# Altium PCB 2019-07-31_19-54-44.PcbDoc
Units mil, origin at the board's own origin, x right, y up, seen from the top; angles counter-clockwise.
Board outline 1400 x 2000 mil, 4 copper layers (Top Layer, MidLayer1, MidLayer2, Bottom Layer); 12 components, 5 nets, 24 pads, 20 vias.
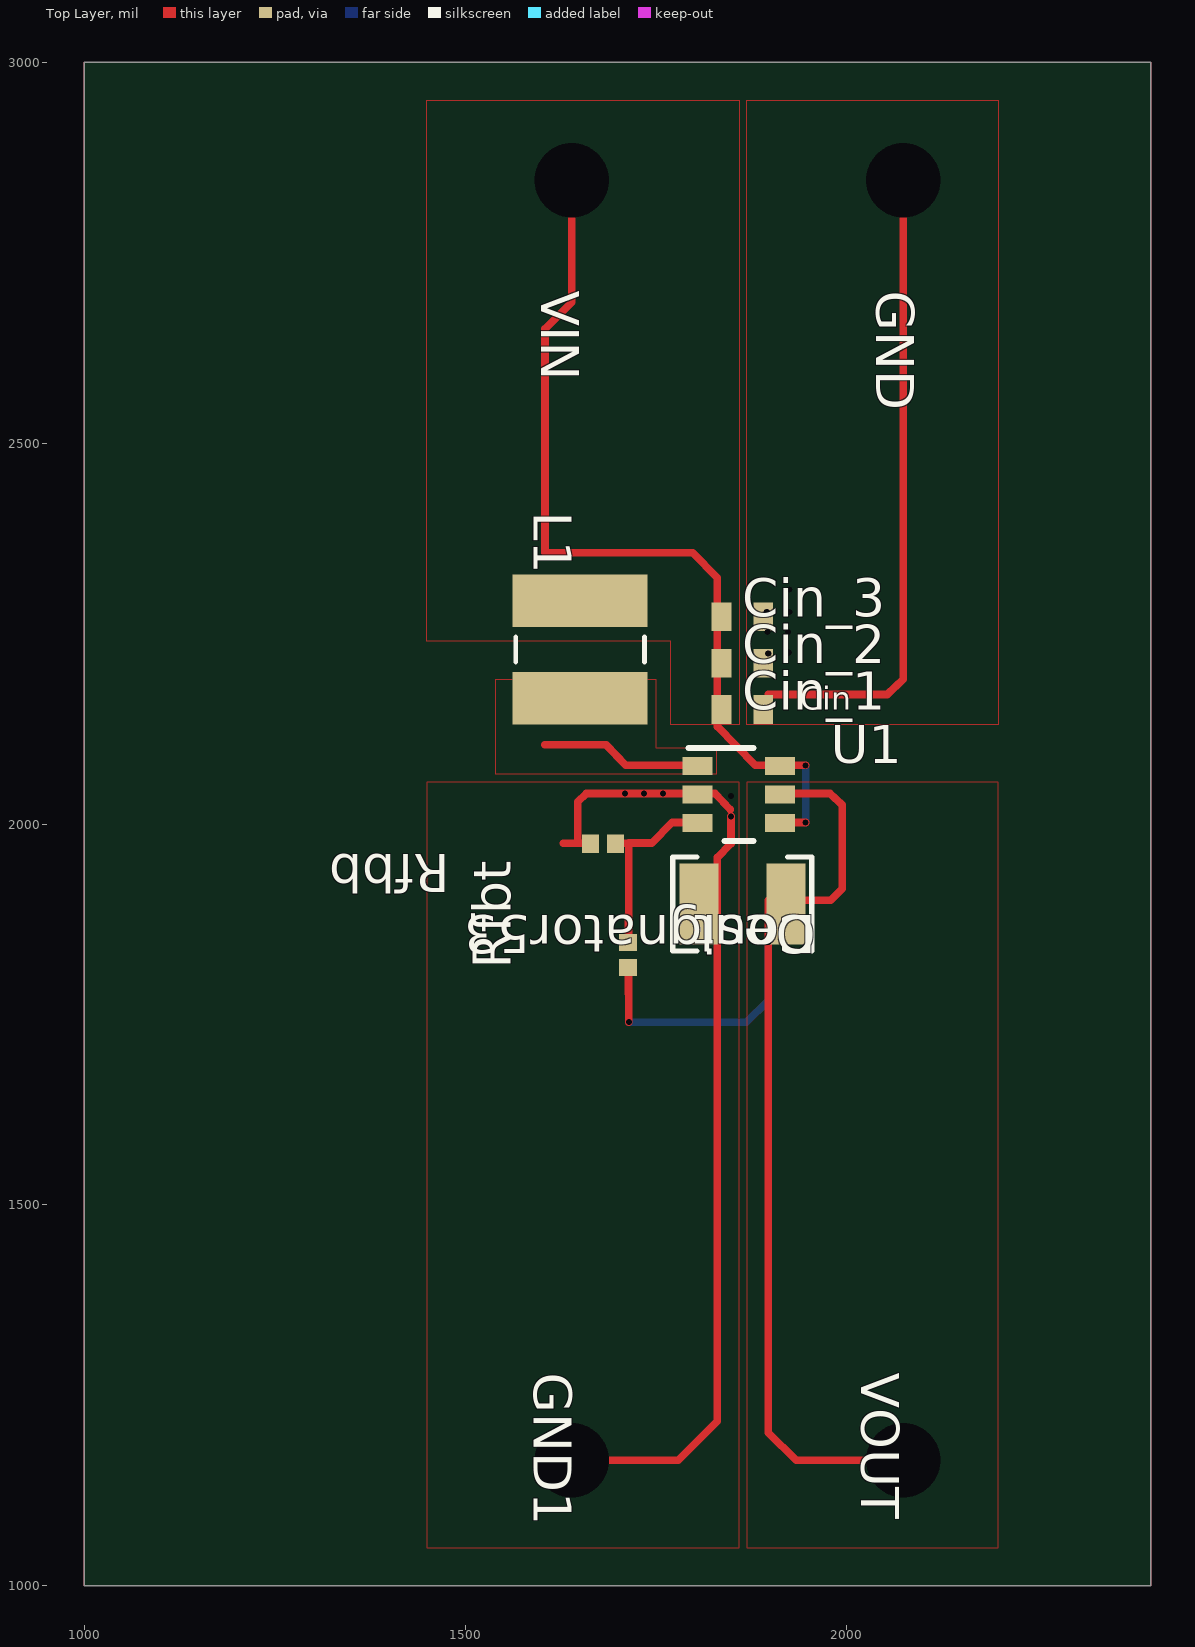
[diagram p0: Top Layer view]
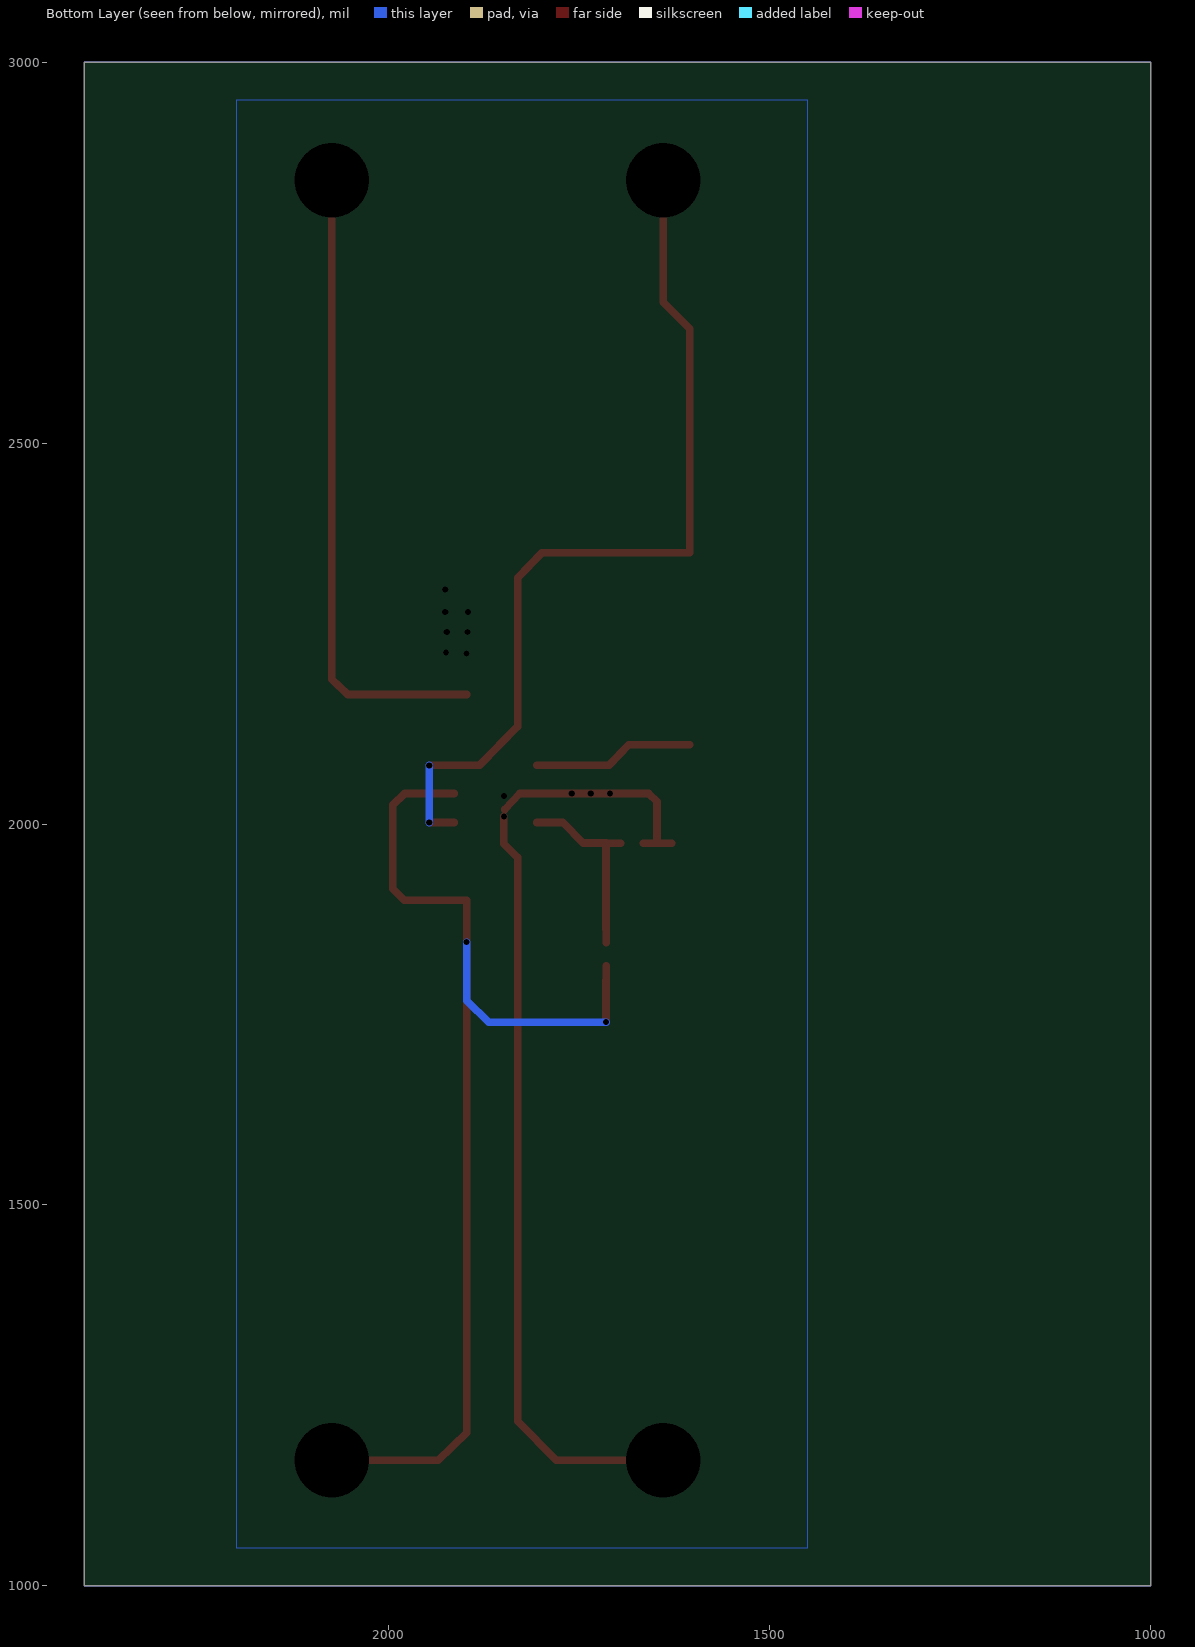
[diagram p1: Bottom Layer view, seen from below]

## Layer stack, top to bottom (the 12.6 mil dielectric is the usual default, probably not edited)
Top Layer: signal copper 1.4
Dielectric: core 12.6, FR-4, Dk 4.8
MidLayer1: signal copper 1.4
Dielectric: prepreg 12.6, FR-4, Dk 4.8
MidLayer2: signal copper 1.4
Dielectric: core 12.6, FR-4, Dk 4.8
Bottom Layer: signal copper 1.4

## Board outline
1000,1000 2400,1000 2400,3000 1000,3000

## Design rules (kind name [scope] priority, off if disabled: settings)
PlaneConnect [All] p0: scope1count=1 scope1_0_kind=Board scope1_0_value=Board scope2count=1 scope2_0_kind=Board scope2_0_value=Board commentlength=0 planeconnectstyle=Direct reliefexpansion=20 reliefentries=4 reliefconductorwidth=10 reliefairgap=10
PlaneConnect [All] p1: planeconnectstyle=Direct reliefexpansion=20 reliefentries=4 reliefconductorwidth=10 reliefairgap=10
PolygonConnect [All] p0: scope1count=1 scope1_0_kind=Board scope1_0_value=Board scope2count=1 scope2_0_kind=Board scope2_0_value=Board commentlength=0 connectstyle=Direct reliefconductorwidth=10 reliefentries=4 polygonreliefangle="90 Angle"
PolygonConnect [All] p1: connectstyle=Direct reliefconductorwidth=10 reliefentries=4 polygonreliefangle="90 Angle"

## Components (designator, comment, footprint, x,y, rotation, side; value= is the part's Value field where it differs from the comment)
Cin_1 "" 0603 1864,2150 r0 top
Cin_2 "" 0603 1864,2211 r0 top
Cin_3 "" 0603 1864,2272 r0 top
Cout "" 1210_270 1864,1895 r180 top
GND "" TP-1502 2074,2844 r270 top
GND1 "" TP-1502 1639,1164 r270 top
L1 "" IND_NPI43C 1651,2229 r270 top
Rfbb "" 0402 1681,1974 r180 top
Rfbt "" 0402 1714,1828 r90 top
U1 "" DBV0006A 1859,2039 r0 top
VIN "" TP-1502 1639,2844 r270 top
VOUT "" TP-1502 2074,1164 r270 top

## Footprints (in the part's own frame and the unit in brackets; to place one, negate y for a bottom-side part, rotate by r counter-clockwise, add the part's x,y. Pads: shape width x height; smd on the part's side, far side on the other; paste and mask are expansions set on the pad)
0402 [mil]
  rect 22x24 smd: 1(-16.5,0) 2(16.5,0)
0603 [mil]
  rect 26x38 smd: 1(-27.5,0) 2(27.5,0)
1210_270 [mm]
  rect 1.3x2.7 smd: 1(-1.45,0) 2(1.45,0)
  silkscreen extent -2.32,-1.57 2.32,1.57
DBV0006A [mm]
  rect 1x0.6 smd: 1(-1.375,0.95) 2(-1.375,0) 3(-1.375,-0.95) 4(1.375,-0.95) 5(1.375,0) 6(1.375,0.95)
  silkscreen extent -1.68,-1.55 0.5,1.55
IND_NPI43C [mil]
  rect 69x177 smd: 1(-64,0) 2(64,0)
  silkscreen extent -16,-84 16,84
TP-1502 [mil]
  round 65 / inner round 0 / far side round 65 hole 32: 1(0,0)

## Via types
v1: diameter 0, hole 8, Top Layer to Bottom Layer, 16 vias
v2: diameter 0, hole 98, Top Layer to Bottom Layer, 4 vias

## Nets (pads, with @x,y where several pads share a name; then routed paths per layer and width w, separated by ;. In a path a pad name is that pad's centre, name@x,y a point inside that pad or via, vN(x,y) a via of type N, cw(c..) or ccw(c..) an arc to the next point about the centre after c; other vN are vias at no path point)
0: Cin_1.2 Cin_2.2 Cin_3.2 Cout.2 GND1.1 GND.1 Rfbb.2 U1.2 | length 2158.1
  Top Layer w10: 1629,1974.5 Rfbb.2@1666,1974.5 ; v2(1640,1165) 1780,1165 1831,1216 1831,1900 1831,1956 1849,1974 v1(1849,2010) ; 1648,1975 1648,2029 1659,2040 v1(1735,2040) 1806,2040 1828,2040 1848,2019 ; 1898,2170 2054,2170 2075,2190 2075,2844 v2(2075,2845)
  other v1: 1849,2037 1710,2040 1760,2040 1898,2224 1925,2225 1897,2252 1924,2252 1896,2278 1926,2278 1926,2308
2: Cin_1.1 Cin_2.1 Cin_3.1 L1.1 U1.4 U1.6 VIN.1 | length 1183.9
  Top Layer w10: v2(1640,2845) 1640,2685 1605,2650 1605,2356 1799,2356 1831,2323 1831,2170 1831,2128 1881,2077 1914,2077 v1(1947,2077) ; U1.4@1914,2002 v1(1947,2002)
  Bottom Layer w10: v1(1947,2002) v1(1947,2077)
3: Cout.1 Rfbt.1 U1.5 VOUT.1 | length 1554.1
  Top Layer w10: 1714.5,1777 Rfbt.1@1714.5,1814 ; v1(1715,1740) 1715,1795 ; U1.5@1914,2040 1979,2040 1995,2025 1995,1915 1980,1900 1898,1900 v1(1898,1845) 1898,1201 1935,1165 v2(2075,1165)
  Bottom Layer w10: v1(1715,1740) 1869,1740 1898,1768 v1(1898,1845)
4: Rfbb.1 Rfbt.2 U1.3 | length 289.2
  Top Layer w10: Rfbb.1@1696,1974.5 1733,1974.5 ; Rfbt.2@1714.5,1844 1714.5,1881 ; 1715,1862 1715,1974 1715,1975 1745,1975 1772,2002 U1.3@1806,2002
5: L1.2 U1.1 | length 212.5
  Top Layer w10: 1605,2104 1685,2104 1711,2077 U1.1@1806,2077

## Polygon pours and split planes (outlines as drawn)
5 on Top Layer " " (solid, pour order 0): 1830,2065 1540,2065 1540,2190 1750,2190 1750,2100 1830,2100
2 on Top Layer " " (solid, pour order 1): 1860,2950 1860,2130 1770,2130 1770,2240 1450,2240 1450,2950
3 on Top Layer " " (solid, pour order 2): 2200,2055 1870,2055 1870,1050 2200,1050
0 on Top Layer " " (solid, pour order 4): 1860,2055 1450,2055 1450,1050 1860,1050
0 on Top Layer " " (solid, pour order 5): 2200,2950 2200,2130 1870,2130 1870,2950
0 on Bottom Layer " " (solid, pour order 3): 2200,2950 2200,1050 1450,1050 1450,2950

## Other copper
Multi-Layer:
  the board outline again, w1

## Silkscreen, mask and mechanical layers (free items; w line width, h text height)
Top Overlay:
  text "Cin" at 1940,2150 h30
